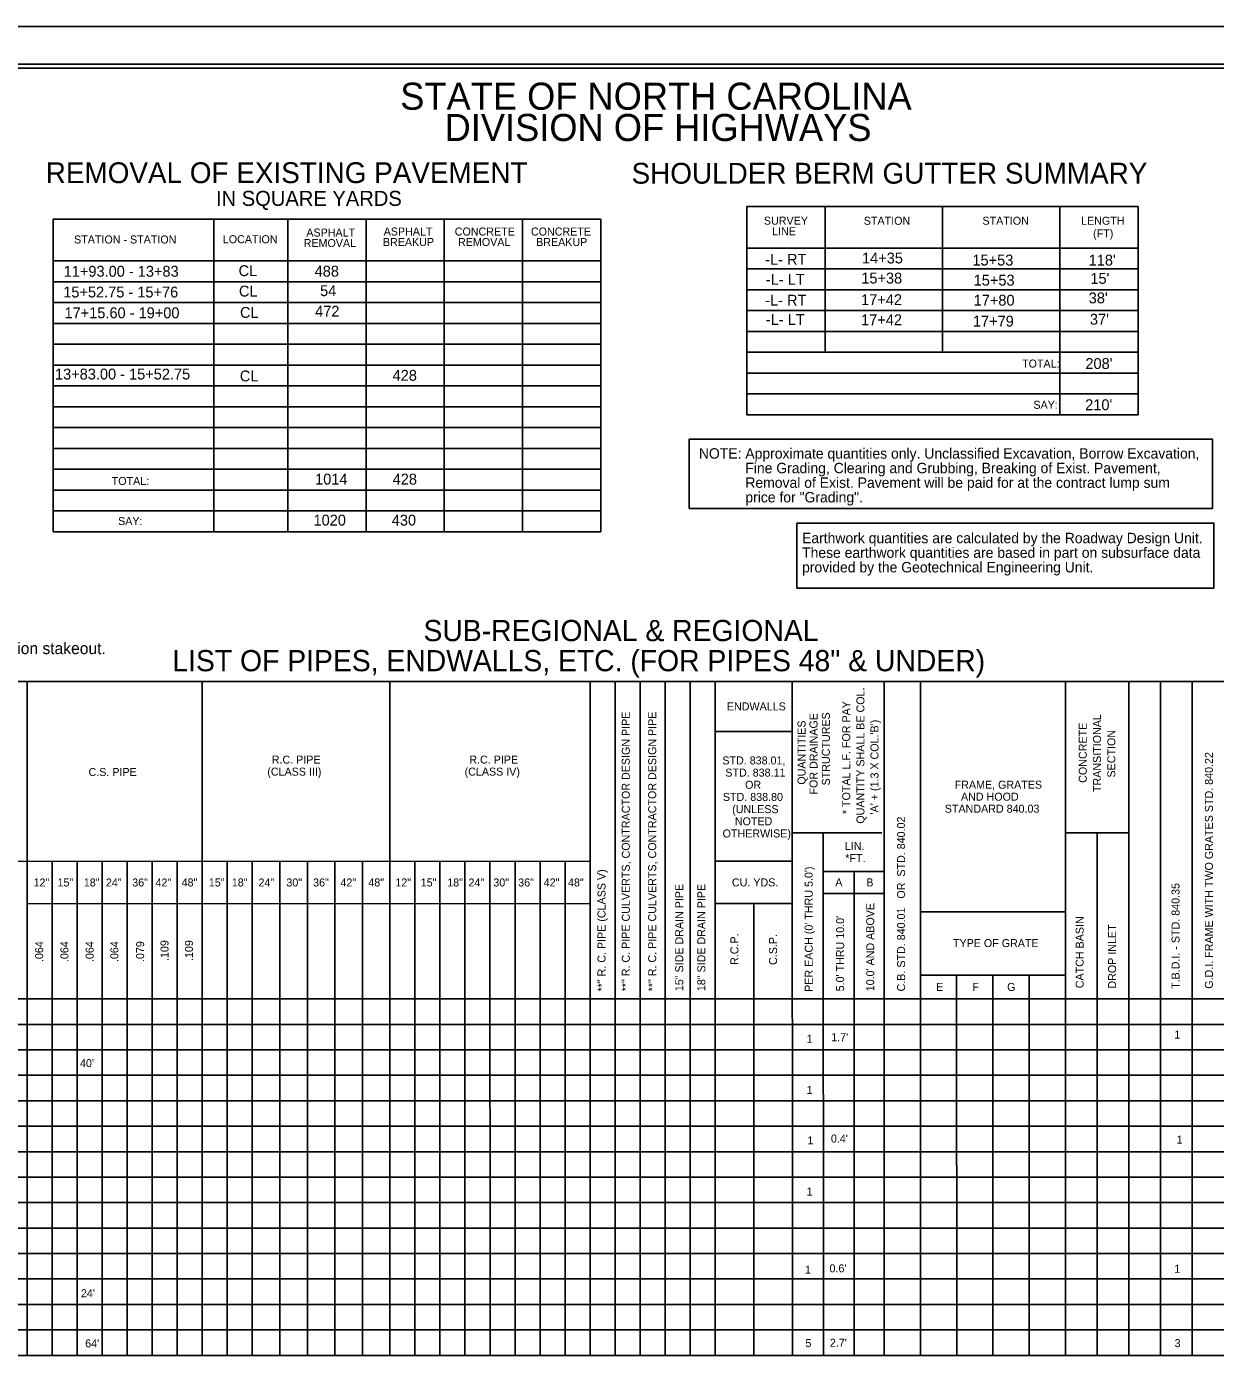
# Model space of a CAD drawing. Extents: x 573359 to 575895, y -54193 to -50493.
# Drawn here: x 574168 to 574880, y -51292 to -50493 of the extents above; entities that cross this region are included whole.
import ezdxf

# ---------------------------------------------------------------- set-up
doc = ezdxf.new("R2010")
doc.units = 0
for name, color, linetype in [('Prop Dimension Text', 7, 'Continuous'), ('Sheet Cutting Line CELL', 7, 'Continuous'), ('Sheet Pipe Summary CELL', 7, 'Continuous'), ('Sheet Pipe Summary Grid CELL', 7, 'Continuous'), ('Sheet Plot Border Inside CELL', 7, 'Continuous'), ('Sheet Plot Border Outside CELL', 7, 'Continuous'), ('Sheet Summary Combination CELL', 7, 'Continuous'), ('Sheet Summary Combination Grid CELL', 7, 'Continuous'), ('Sheet Summary Earthwork CELL', 7, 'Continuous')]:
    doc.layers.add(name, color=color, linetype=linetype)

msp = doc.modelspace()

# ---------------------------------------------------------------- linework, layer by layer
at = {"layer": 'Sheet Cutting Line CELL'}
msp.add_line((575286.01, -50493.3), (573602.01, -50493.3), dxfattribs=at)
at = {"layer": 'Sheet Pipe Summary Grid CELL'}
for p, q in [((575269.01, -50886), (573769.01, -50886.1)), ((574168.08, -51290.2), (574168.06, -50886.07)), ((574273.08, -51290.2), (574273.06, -50886.07)), ((574385.6, -51290.2), (574385.56, -50885.99)), ((574505.6, -51290.2), (574505.56, -50886)), ((574520.6, -51290.2), (574520.56, -50886)), ((574535.6, -51290.2), (574535.56, -50886)), ((574550.6, -51290.2), (574550.56, -50886)), ((574565.6, -51290.2), (574565.56, -50885.99)), ((574580.6, -51290.2), (574580.56, -50885.99)), ((574580.58, -51290.2), (574580.56, -50885.99)), ((574580.6, -51290.2), (574580.56, -50885.99)), ((574626.85, -51290.2), (574626.81, -50886.04)), ((574681.85, -51290.2), (574681.81, -50886.04)), ((574681.85, -51290.2), (574681.81, -50886.04)), ((574703.68, -51290.2), (574703.66, -50886.04)), ((574790.63, -51290.2), (574790.61, -50886.04)), ((574828.63, -51290.2), (574828.61, -50886.04)), ((574847.63, -51290.2), (574847.61, -50886.04)), ((574866.63, -51290.2), (574866.61, -50886.04)), ((574626.81, -50915.99), (574580.56, -50915.99)), ((574680.56, -50976.74), (574626.82, -50976.74)), ((574645.44, -51290.2), (574645.41, -50976.74)), ((574828.61, -50976.74), (574790.61, -50976.74)), ((574809.63, -51290.2), (574809.61, -50976.74)), ((574505.57, -50993.87), (573988.07, -50993.95)), ((574183.08, -51290.2), (574183.07, -50993.93)), ((574198.08, -51290.2), (574198.07, -50993.92)), ((574213.08, -51290.2), (574213.07, -50993.93)), ((574228.08, -51290.2), (574228.07, -50993.91)), ((574243.08, -51290.2), (574243.07, -50993.93)), ((574258.08, -51290.2), (574258.07, -50993.91)), ((574273.08, -51290.2), (574273.07, -50993.93)), ((574288.08, -51290.2), (574288.07, -50993.9)), ((574303.08, -51290.2), (574303.07, -50993.9)), ((574319.58, -51290.2), (574319.57, -50993.9)), ((574336.08, -51290.2), (574336.07, -50993.9)), ((574352.58, -51290.2), (574352.57, -50993.9)), ((574369.08, -51290.2), (574369.07, -50993.9)), ((574385.58, -51290.2), (574385.57, -50993.9)), ((574400.58, -51290.2), (574400.57, -50993.89)), ((574415.58, -51290.2), (574415.57, -50993.89)), ((574430.58, -51290.2), (574430.57, -50993.89)), ((574445.58, -51290.2), (574445.57, -50993.89)), ((574460.58, -51290.2), (574460.57, -50993.89)), ((574475.58, -51290.2), (574475.57, -50993.89)), ((574490.58, -51290.2), (574490.57, -50993.89)), ((574505.58, -51290.2), (574505.57, -50993.89)), ((574626.81, -50993.84), (574580.56, -50993.84)), ((574681.81, -50999.94), (574645.41, -50999.94)), ((574663.99, -51290.2), (574663.96, -50999.94)), ((574505.57, -51019.28), (574168.07, -51019.31)), ((574168.08, -51290.2), (574168.07, -51019.31)), ((574626.81, -51019.24), (574580.56, -51019.24)), ((574603.72, -51290.2), (574603.71, -51019.24)), ((574681.81, -51013.14), (574645.41, -51013.14)), ((574790.61, -51024.29), (574703.66, -51024.29)), ((574790.61, -51062.09), (574703.66, -51062.09)), ((574725.39, -51290.2), (574725.36, -51062.09)), ((574747.12, -51290.2), (574747.11, -51062.09)), ((574768.91, -51290.2), (574768.91, -51062.09)), ((575269.01, -51076.4), (573769.01, -51076.4)), ((575269.01, -51091.7), (573769.01, -51091.7)), ((575269.01, -51106.95), (573769.01, -51106.95)), ((575269.01, -51122.2), (573769.01, -51122.2)), ((575269.01, -51137.5), (573769.01, -51137.5)), ((575269.01, -51152.75), (573769.01, -51152.75)), ((575269.01, -51168.05), (573769.01, -51168.05)), ((575269.01, -51183.3), (573769.01, -51183.3)), ((575269.01, -51198.55), (573769.01, -51198.55)), ((575269.01, -51213.85), (573769.01, -51213.85)), ((575269.01, -51213.85), (573769.01, -51213.85)), ((575269.01, -51229.1), (573769.01, -51229.1)), ((575269.01, -51244.4), (573769.01, -51244.4)), ((575269.01, -51259.65), (573769.01, -51259.65)), ((575269.01, -51274.9), (573769.01, -51274.9)), ((575269.01, -51274.9), (573769.01, -51274.9)), ((575269.01, -51290.2), (573769.01, -51290.2)), ((575269.01, -51290.2), (573769.01, -51290.2))]:
    msp.add_line(p, q, dxfattribs=at)
at = {"layer": 'Sheet Plot Border Inside CELL'}
msp.add_lwpolyline([(575281.51, -50515.75), (573615.01, -50515.75), (573615.01, -51570.85), (575281.51, -51570.85)], close=True, dxfattribs=at)
at = {"layer": 'Sheet Plot Border Outside CELL'}
msp.add_lwpolyline([(575286.01, -50493.3), (573602.01, -50493.3), (573602.01, -51593.3), (575286.01, -51593.3)], close=True, dxfattribs=at)
at = {"layer": 'Sheet Summary Combination CELL'}
for p, q in [((574740.91, -50601.14), (574740.91, -50601.14)), ((574747.16, -50601.24), (574747.16, -50601.24)), ((574756.21, -50601.04), (574756.21, -50601.04)), ((574761.81, -50601.14), (574761.81, -50601.14)), ((574278.09, -50608.84), (574278.09, -50608.84)), ((574284.34, -50608.94), (574284.34, -50608.94)), ((574293.39, -50608.74), (574293.39, -50608.74)), ((574298.99, -50608.84), (574298.99, -50608.84))]:
    msp.add_line(p, q, dxfattribs=at)
msp.add_lwpolyline([(575269.01, -50518.3), (573769.01, -50518.3), (573769.01, -51568.3), (575269.01, -51568.3)], close=True, dxfattribs=at)
at = {"layer": 'Sheet Summary Combination Grid CELL'}
for p, q in [((574599.66, -50601.09), (574834.11, -50601.09)), ((574599.66, -50601.09), (574599.66, -50726.09)), ((574646.56, -50601.09), (574646.56, -50688.59)), ((574716.91, -50601.09), (574716.91, -50688.59)), ((574787.21, -50601.09), (574787.21, -50726.09)), ((574834.11, -50601.09), (574834.11, -50726.09)), ((574183.74, -50608.79), (574511.99, -50608.79)), ((574183.74, -50608.79), (574183.74, -50796.29)), ((574280.08, -50608.79), (574280.08, -50796.29)), ((574324.39, -50608.79), (574324.39, -50796.29)), ((574371.29, -50608.79), (574371.29, -50796.29)), ((574418.19, -50608.79), (574418.19, -50796.29)), ((574465.09, -50608.79), (574465.09, -50796.29)), ((574511.99, -50608.79), (574511.99, -50796.29)), ((574599.66, -50626.09), (574834.11, -50626.09)), ((574183.74, -50633.79), (574511.99, -50633.79)), ((574599.66, -50638.59), (574834.11, -50638.59)), ((574183.74, -50646.29), (574511.99, -50646.29)), ((574599.66, -50651.09), (574834.11, -50651.09)), ((574183.74, -50658.79), (574511.99, -50658.79)), ((574599.66, -50663.59), (574834.11, -50663.59)), ((574183.74, -50671.29), (574511.99, -50671.29)), ((574599.66, -50676.09), (574834.11, -50676.09)), ((574183.74, -50683.79), (574511.99, -50683.79)), ((574599.66, -50688.59), (574834.11, -50688.59)), ((574183.74, -50696.29), (574511.99, -50696.29)), ((574599.66, -50701.09), (574834.11, -50701.09)), ((574183.74, -50708.79), (574511.99, -50708.79)), ((574599.66, -50713.59), (574834.11, -50713.59)), ((574183.74, -50721.29), (574511.99, -50721.29)), ((574599.66, -50726.09), (574834.11, -50726.09)), ((574183.74, -50733.79), (574511.99, -50733.79)), ((574183.74, -50746.29), (574511.99, -50746.29)), ((574183.74, -50758.79), (574511.99, -50758.79)), ((574183.74, -50771.29), (574511.99, -50771.29)), ((574183.74, -50783.79), (574511.99, -50783.79)), ((574183.74, -50796.29), (574511.99, -50796.29))]:
    msp.add_line(p, q, dxfattribs=at)
at = {"layer": 'Sheet Summary Earthwork CELL'}
for points in [[(574565.02, -50740.63), (574878.72, -50740.63), (574878.72, -50782.21), (574565.02, -50782.21)], [(574629.55, -50791.02), (574879.61, -50791.02), (574879.61, -50830.05), (574629.55, -50830.05)]]:
    msp.add_lwpolyline(points, close=True, dxfattribs=at)

# ---------------------------------------------------------------- texts
at = {"layer": 'Prop Dimension Text'}
for s, height, p in [('-L- RT', 6.528, (574610.56, -50636.13)), ('14+35', 6.528, (574668.63, -50635.33)), ('11+93.00 - 13+83', 6.528, (574189.98, -50643.29)), ('CL', 6.528, (574294.87, -50642.93)), ('488', 6.528, (574340.43, -50643.22)), ('15+53', 6.528, (574734.84, -50636.58)), ("118'", 6.528, (574804.53, -50636.58)), ('-L- LT', 6.528, (574610.94, -50648.12)), ('15+38', 6.528, (574668.18, -50647.37)), ('15+53', 6.528, (574735.59, -50648.62)), ("15'", 6.528, (574805.56, -50647.56)), ('15+52.75 - 15+76', 6.528, (574189.71, -50655.75)), ('CL', 6.528, (574295.06, -50655.19)), ('54', 6.528, (574343.71, -50654.95)), ("38'", 6.528, (574804.56, -50659.28)), ('17+15.60 - 19+00', 6.528, (574190.47, -50668.2)), ('CL', 6.528, (574295.7, -50667.97)), ('472', 6.528, (574340.74, -50667.25)), ('-L- RT', 6.528, (574610.56, -50660.66)), ('17+42', 6.528, (574668.07, -50660.33)), ('17+80', 6.528, (574735.57, -50660.65)), ('-L- LT', 6.528, (574610.94, -50672.2)), ('17+42', 6.528, (574668.07, -50672.37)), ('17+79', 6.528, (574735.12, -50673.19)), ("37'", 6.528, (574805.29, -50672.06)), ("208'", 6.528, (574802.56, -50698.62)), ('13+83.00 - 15+52.75', 6.528, (574184.76, -50704.94)), ('CL', 6.528, (574295.59, -50706.06)), ('428', 6.528, (574387.18, -50705.69)), ("210'", 6.528, (574802.44, -50723.34)), ('1014', 6.528, (574340.73, -50767.93)), ('428', 6.528, (574387.23, -50767.93)), ('1020', 6.528, (574339.77, -50792.52)), ('430', 6.528, (574386.66, -50792.52)), ('1', 4.8, (574635.4, -51102.74)), ("1.7'", 4.8, (574650.16, -51101.77)), ('1', 4.8, (574855.81, -51100.26)), ("40'", 4.8, (574199.76, -51117.33)), ('1', 4.8, (574635.4, -51133.42)), ('1', 4.8, (574635.89, -51163.65)), ("0.4'", 4.8, (574649.99, -51162.55)), ('1', 4.8, (574857.26, -51163.17)), ('1', 4.8, (574635.4, -51194.37)), ('1', 4.8, (574634.44, -51241.19)), ("0.6'", 4.8, (574649.13, -51240.41)), ('1', 4.8, (574855.81, -51240.7)), ("24'", 4.8, (574200.31, -51255.33)), ("64'", 4.8, (574202.86, -51285.45)), ('5', 4.8, (574634.71, -51285.28)), ("2.7'", 4.8, (574649.38, -51285.03)), ('3', 4.8, (574856.07, -51285.28))]:
    msp.add_text(s, height=height, dxfattribs=at).set_placement(p)
at = {"layer": 'Sheet Pipe Summary CELL'}
for s, height, p in [('SUB-REGIONAL & REGIONAL', 12.6999, (574405.69, -50861.85)), ('NOTE: Invert Elevations are for Bid Purposes only and shall not be used for project construction stakeout.', 7, (573777.65, -50869.64)), ('LIST OF PIPES, ENDWALLS, ETC. (FOR PIPES 48" & UNDER)', 12.6999, (574255.12, -50879.9)), ('ENDWALLS', 4.8, (574587.61, -50903.39)), ('R.C. PIPE', 4.8, (574314.74, -50935.31)), ('R.C. PIPE', 4.8, (574433.2, -50935.31)), ('STD. 838.01,', 4.8, (574584.88, -50935.79)), ('C.S. PIPE', 4.8, (574204.88, -50942.74)), ('(CLASS III)', 4.8, (574312.06, -50942.51)), ('(CLASS IV)', 4.8, (574430.36, -50942.51)), ('STD. 838.11', 4.8, (574586.68, -50943.09)), ('OR', 4.8, (574598.53, -50950.39)), ('FRAME, GRATES', 4.8, (574724.16, -50950.34)), ('STD. 838.80', 4.8, (574585.21, -50957.69)), ('AND HOOD', 4.8, (574727.96, -50957.54)), ('(UNLESS', 4.8, (574590.78, -50964.99)), ('STANDARD 840.03', 4.8, (574718.26, -50964.74)), ('NOTED', 4.8, (574592.38, -50972.29)), ('OTHERWISE)', 4.8, (574585.03, -50979.59)), ('LIN.', 4.8, (574658.31, -50987.09)), ('*FT.', 4.8, (574658.61, -50994.39)), ('12"', 4.8, (574171.9, -51008.99)), ('15"', 4.8, (574186.26, -51008.99)), ('18"', 4.8, (574202.05, -51008.99)), ('24"', 4.8, (574215.29, -51008.99)), ('36"', 4.8, (574231.08, -51008.99)), ('42"', 4.8, (574245.02, -51008.99)), ('48"', 4.8, (574260.69, -51008.99)), ('15"', 4.8, (574277.01, -51008.99)), ('18"', 4.8, (574290.79, -51008.99)), ('24"', 4.8, (574306.77, -51008.99)), ('30"', 4.8, (574323.49, -51008.99)), ('36"', 4.8, (574339.53, -51008.99)), ('42"', 4.8, (574355.91, -51008.99)), ('48"', 4.8, (574372.63, -51008.99)), ('12"', 4.8, (574388.85, -51008.99)), ('15"', 4.8, (574404.05, -51008.99)), ('18"', 4.8, (574419.95, -51008.99)), ('24"', 4.8, (574432.67, -51008.99)), ('30"', 4.8, (574447.58, -51008.99)), ('36"', 4.8, (574462.5, -51008.99)), ('42"', 4.8, (574477.78, -51008.99)), ('48"', 4.8, (574492.34, -51008.99)), ('CU. YDS.', 4.8, (574590.61, -51008.94)), ('A', 4.8, (574652.61, -51008.94)), ('B', 4.8, (574671.21, -51008.94)), ('TYPE OF GRATE', 4.8, (574723.16, -51045.34)), ('E', 4.8, (574713.01, -51071.64)), ('F', 4.8, (574734.76, -51071.64)), ('G', 4.8, (574755.66, -51071.64))]:
    msp.add_text(s, height=height, dxfattribs=at).set_placement(p)
for s, height, rotation, p in [('QUANTITY SHALL BE COL.', 4.8, 90, (574670.06, -50971.34)), ('* TOTAL L.F. FOR PAY', 4.8, 90, (574661.56, -50965.59)), ('**" R. C. PIPE CULVERTS, CONTRACTOR DESIGN PIPE', 4.8, 90, (574529.39, -51071.87)), ('**" R. C. PIPE CULVERTS, CONTRACTOR DESIGN PIPE', 4.8, 90, (574545.22, -51071.87)), ('FOR DRAINAGE', 4.8, 90, (574641.96, -50953.84)), ('STRUCTURES', 4.8, 90, (574649.36, -50948.39)), ('TRANSITIONAL', 4.8, 90, (574811.94, -50952.36)), ('QUANTITIES', 4.8, 90, (574634.76, -50947.94)), ("'A' + (1.3 X COL.'B')", 4.8, 90, (574678.51, -50965.79)), ('CONCRETE', 4.8, 90, (574803.39, -50946.82)), ('SECTION', 4.8, 90, (574820.49, -50943.65)), ('G.D.I. FRAME WITH TWO GRATES STD. 840.22', 4.8, 90, (574879.02, -51070.33)), ('C.B. STD. 840.01   OR  STD. 840.02', 4.8, 90, (574694.46, -51071.94)), ('**" R. C. PIPE (CLASS V)', 4.8, 90, (574514.83, -51071.97)), ("PER EACH (0' THRU 5.0')", 4.7986, 90.03687, (574639.11, -51072.19)), ('15" SIDE DRAIN PIPE', 4.8, 90, (574561.44, -51071.77)), ('18" SIDE DRAIN PIPE', 4.8, 90, (574574.68, -51071.77)), ('T.B.D.I. - STD. 840.35', 4.8, 90, (574859.01, -51070.42)), ("10.0' AND ABOVE", 4.8, 90, (574675.96, -51071.84)), ("5.0' THRU 10.0'", 4.8, 90, (574657.91, -51071.89)), ('CATCH BASIN', 4.8, 90, (574801.52, -51070.01)), ('DROP INLET', 4.8, 90, (574820.96, -51070.24)), ('.064', 4.8, 90, (574177.68, -51054.32)), ('.064', 4.8, 90, (574192.81, -51054.32)), ('.064', 4.8, 90, (574207.94, -51054.32)), ('.064', 4.8, 90, (574222.75, -51054.32)), ('.079', 4.8, 90, (574238.21, -51054.29)), ('.109', 4.8, 90, (574252.84, -51053.69)), ('.109', 4.8, 90, (574267.49, -51053.69)), ('R.C.P.', 4.8, 90, (574594.51, -51056.04)), ('C.S.P.', 4.8, 90, (574617.66, -51056.04))]:
    msp.add_text(s, height=height, rotation=rotation, dxfattribs=at).set_placement(p)
at = {"layer": 'Sheet Summary Combination CELL'}
for s, height, p in [('STATE OF NORTH CAROLINA', 16.2501, (574391.76, -50543.15)), ('DIVISION OF HIGHWAYS', 16.2501, (574418.36, -50561.9)), ('SURVEY', 4.8, (574609.81, -50612.08)), ('LINE', 4.8, (574614.71, -50618.38)), ('STATION', 4.8, (574669.71, -50612.13)), ('STATION', 4.8, (574740.85, -50612.11)), ('LENGTH', 4.8, (574799.97, -50612.11)), ('STATION - STATION', 4.8, (574196.21, -50623.35)), ('LOCATION', 4.8, (574285.39, -50623.21)), ('REMOVAL', 4.8, (574333.87, -50625.49)), ('ASPHALT', 4.8, (574335.47, -50619.19)), ('(FT)', 4.8, (574807.17, -50619.72)), ('TOTAL:', 4.8, (574764.6, -50697.78)), ('SAY:', 4.8, (574771.39, -50722.49)), ('TOTAL:', 4.8, (574218.77, -50768.19)), ('SAY:', 4.8, (574222.58, -50792.22))]:
    msp.add_text(s, height=height, dxfattribs=at).set_placement(p)
for s, height, p in [('REMOVAL OF EXISTING PAVEMENT', 12.5001, (574179.22, -50587.18)), ('SHOULDER BERM GUTTER SUMMARY', 12.5001, (574530.45, -50587.5)), ('IN SQUARE YARDS', 9.0313, (574281.29, -50600.83))]:
    msp.add_text(s, height=height, rotation=0.01193, dxfattribs=at).set_placement(p)
at = {"layer": 'Sheet Summary Combination Grid CELL'}
for s, p in [('ASPHALT', (574381.83, -50618.58)), ('BREAKUP', (574381.34, -50624.88)), ('CONCRETE', (574424.45, -50618.58)), ('REMOVAL', (574426.42, -50624.88)), ('CONCRETE', (574470.14, -50618.58)), ('BREAKUP', (574473.23, -50624.88))]:
    msp.add_text(s, height=4.8, dxfattribs=at).set_placement(p)
at = {"layer": 'Sheet Summary Earthwork CELL'}
for s, p in [('NOTE: Approximate quantities only. Unclassified Excavation, Borrow Excavation,', (574570.81, -50752.4)), ('            Fine Grading, Clearing and Grubbing, Breaking of Exist. Pavement,', (574570.81, -50761.15)), ('            Removal of Exist. Pavement will be paid for at the contract lump sum', (574570.81, -50769.9)), ('            price for "Grading".', (574570.81, -50778.65)), ('Earthwork quantities are calculated by the Roadway Design Unit. ', (574632.68, -50803.13)), ('These earthwork quantities are based in part on subsurface data ', (574632.68, -50811.88)), ('provided by the Geotechnical Engineering Unit.', (574632.68, -50820.63))]:
    msp.add_text(s, height=6.25, dxfattribs=at).set_placement(p)

doc.saveas('drawing.dxf')
